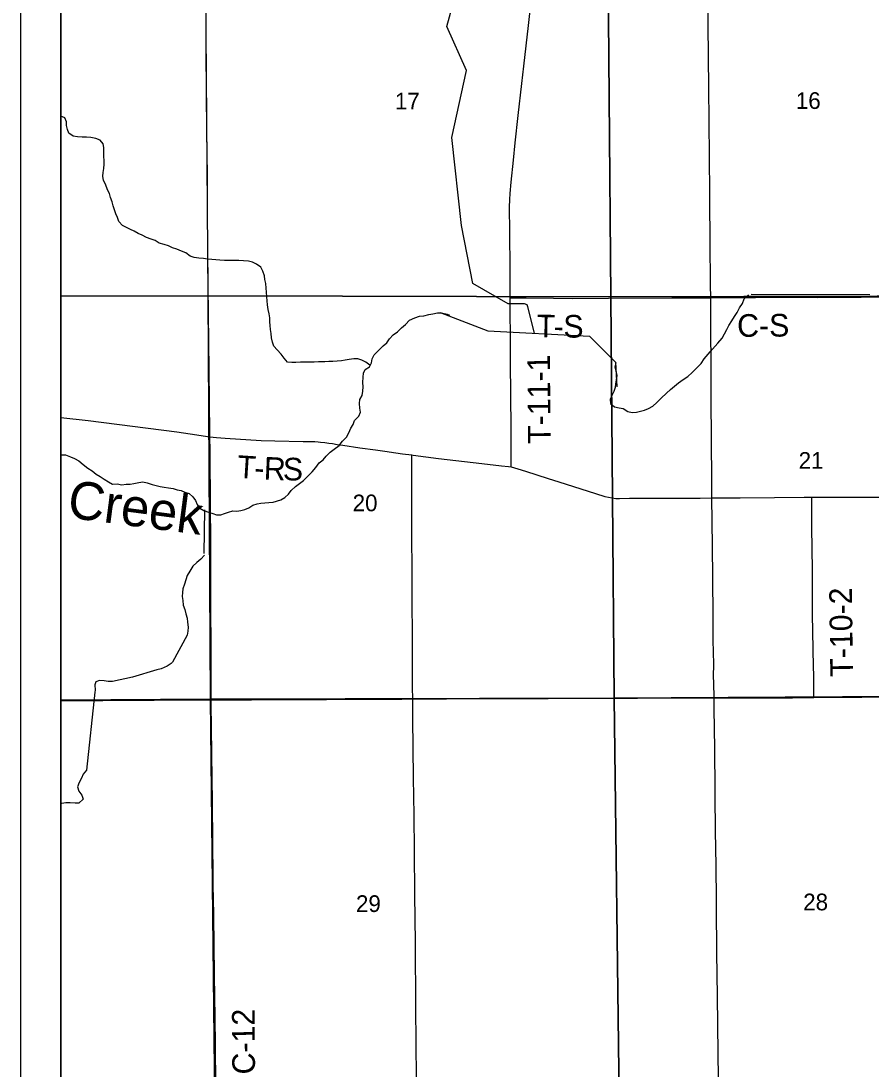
# Model space of a CAD drawing. Extents: x 0 to 34, y 0 to 22.
# Drawn here: x 23.417 to 25.546, y 16.699 to 19.326 of the extents above; entities that cross this region are included whole.
import ezdxf

# ---------------------------------------------------------------- set-up
doc = ezdxf.new("R2010")
doc.units = 0
for name, color, linetype in [('GM_X_County_Road', 7, 'Continuous'), ('GM_X_County_Road_Text', 7, 'Continuous'), ('GM_X_Minor_River', 7, 'Continuous'), ('GM_X_Minor_River_Text', 7, 'Continuous'), ('GM_X_Section', 7, 'Continuous'), ('GM_X_Section_Text', 7, 'Continuous'), ('GM_X_Township_Road', 7, 'Continuous'), ('GM_X_Township_Road_Text', 7, 'Continuous'), ('GM_X_US_Route', 7, 'Continuous'), ('SC_Scratch1', 7, 'Continuous'), ('SH_Data', 7, 'Continuous')]:
    doc.layers.add(name, color=color, linetype=linetype)

msp = doc.modelspace()

# ---------------------------------------------------------------- linework, layer by layer
at = {"layer": 'GM_X_County_Road'}
for points in [[(23.8901, 18.2832), (23.89, 18.2923), (23.8882, 18.4509), (23.886, 18.6623), (23.8844, 18.8488), (23.8839, 18.9265), (23.8836, 18.9483), (23.8833, 18.9825), (23.8824, 19.0602), (23.8818, 19.1348), (23.881, 19.2623), (23.8805, 19.3369), (23.8781, 19.5887), (23.8777, 19.6313)], [(25.1452, 18.632), (25.1445, 18.6646), (25.1437, 18.7733), (25.1433, 18.8012), (25.1429, 18.8477), (25.1424, 18.8944), (25.1408, 19.0747), (25.1401, 19.1582), (25.1393, 19.2357), (25.1387, 19.3165), (25.1382, 19.3693), (25.1379, 19.3812)], [(25.148, 18.1303), (25.1476, 18.1736), (25.1463, 18.3788), (25.1457, 18.4813), (25.1454, 18.5342), (25.1451, 18.6026), (25.1454, 18.6242), (25.1452, 18.632)], [(25.1452, 18.632), (25.2015, 18.6323), (25.2574, 18.6324), (25.304, 18.6331), (25.4128, 18.6328), (25.5216, 18.6336), (25.5869, 18.6341), (25.7485, 18.6348), (25.8945, 18.6357)], [(23.5167, 18.3321), (23.5849, 18.3241), (23.807, 18.2961), (23.8408, 18.2914), (23.8901, 18.2832)], [(23.8934, 17.6243), (23.8936, 17.6615), (23.8933, 17.6926), (23.8933, 17.7641), (23.8926, 17.8481), (23.8926, 17.8884), (23.8921, 17.9411), (23.892, 17.9845), (23.892, 18.0343), (23.8913, 18.0996), (23.8914, 18.1462), (23.8908, 18.2084), (23.8907, 18.2488), (23.8901, 18.2832)], [(25.1534, 17.6295), (25.1523, 17.6673), (25.1521, 17.6827), (25.1524, 17.7136), (25.1513, 17.7739), (25.1511, 17.8329), (25.15, 17.9311), (25.1494, 18.0088), (25.1486, 18.071), (25.148, 18.1303)], [(23.9049, 16.6197), (23.9048, 16.6263), (23.9045, 16.6667), (23.903, 16.8346), (23.9026, 16.875), (23.9006, 17.0056), (23.8996, 17.0864), (23.8985, 17.161), (23.8971, 17.2885), (23.897, 17.3071), (23.8967, 17.3289), (23.8966, 17.3475), (23.8962, 17.3693), (23.8954, 17.4253), (23.8947, 17.4905), (23.8933, 17.6149), (23.8934, 17.6243)], [(25.1644, 16.6302), (25.1644, 16.6391), (25.1641, 16.6764), (25.1634, 16.7386), (25.1617, 16.8816), (25.1603, 16.9903), (25.1593, 17.1051), (25.1592, 17.1327), (25.1575, 17.2632), (25.157, 17.2847), (25.1567, 17.3248), (25.1562, 17.3557), (25.1558, 17.3991), (25.1547, 17.5016), (25.1535, 17.6025), (25.1534, 17.6272), (25.1534, 17.6295)]]:
    msp.add_lwpolyline(points, dxfattribs=at)
at = {"layer": 'GM_X_Minor_River'}
for points in [[(24.7033, 18.543), (24.6869, 18.6095), (24.6851, 18.6141), (24.6779, 18.6168), (24.6673, 18.6169), (24.6369, 18.6164), (24.5484, 18.6678), (24.5208, 18.8134), (24.4962, 19.0334), (24.5329, 19.2019), (24.4836, 19.312), (24.5085, 19.404)], [(23.5477, 19.037), (23.5364, 19.0444), (23.5331, 19.0539), (23.5305, 19.0638), (23.531, 19.0733), (23.5266, 19.0828), (23.5168, 19.0871), (23.5167, 19.0871)], [(24.2907, 18.4635), (24.2809, 18.4704), (24.2711, 18.4758), (24.2606, 18.479), (24.2503, 18.4791), (24.2386, 18.4773), (24.2291, 18.4759), (24.2196, 18.4741), (24.2086, 18.473), (24.1983, 18.472), (24.1881, 18.4721), (24.1778, 18.4718), (24.1623, 18.4712), (24.1513, 18.4702), (24.1407, 18.4703), (24.1285, 18.4708), (24.1168, 18.4705), (24.1054, 18.4699), (24.0956, 18.47), (24.0842, 18.4708), (24.0763, 18.4804), (24.0685, 18.4907), (24.0584, 18.5011), (24.0505, 18.5106), (24.0468, 18.5205), (24.0443, 18.5316), (24.0433, 18.5426), (24.0422, 18.5525), (24.0408, 18.5623), (24.0402, 18.5718), (24.0399, 18.5813), (24.0381, 18.592), (24.0363, 18.603), (24.0345, 18.6144), (24.0335, 18.6247), (24.0329, 18.6341), (24.0319, 18.6463), (24.0312, 18.6562), (24.0298, 18.6676), (24.0276, 18.6778), (24.0266, 18.6873), (24.0229, 18.6988), (24.0174, 18.7091), (24.0068, 18.7164), (23.9966, 18.7214), (23.9864, 18.7238), (23.9739, 18.7247), (23.9626, 18.7252), (23.9508, 18.7257), (23.9375, 18.7258), (23.9265, 18.7251), (23.9148, 18.7264), (23.905, 18.7273), (23.8947, 18.7277), (23.8841, 18.7286), (23.8739, 18.7302), (23.8622, 18.7311), (23.8504, 18.7327), (23.8406, 18.7366), (23.8297, 18.7447), (23.8191, 18.749), (23.8074, 18.7536), (23.7965, 18.7575), (23.7867, 18.7618), (23.7753, 18.7653), (23.7632, 18.7689), (23.7527, 18.7758), (23.7425, 18.7786), (23.7312, 18.7832), (23.7202, 18.789), (23.7104, 18.7929), (23.7006, 18.7991), (23.6908, 18.8034), (23.6712, 18.8134), (23.6618, 18.823), (23.6585, 18.8329), (23.6541, 18.8424), (23.6508, 18.8527), (23.6478, 18.8626), (23.6453, 18.8725), (23.6409, 18.8836), (23.6387, 18.8931), (23.6335, 18.9026), (23.6283, 18.9163), (23.6235, 18.9259), (23.6217, 18.9365), (23.6222, 18.946), (23.6242, 18.9562), (23.6251, 18.9665), (23.6248, 18.9763), (23.6245, 18.9858), (23.6242, 18.9972), (23.624, 19.0082), (23.6226, 19.0177), (23.6147, 19.0273), (23.6045, 19.0308), (23.592, 19.034), (23.5807, 19.0348), (23.57, 19.0345), (23.5579, 19.0354), (23.5477, 19.037)], [(24.9068, 18.4688), (24.9048, 18.4586), (24.9073, 18.4479), (24.9095, 18.4373), (24.9082, 18.4267), (24.9062, 18.4164), (24.9054, 18.407), (24.9018, 18.3971), (24.8968, 18.3869), (24.8929, 18.3767), (24.8936, 18.3668), (24.9041, 18.3588), (24.9151, 18.3564), (24.9256, 18.3544), (24.9373, 18.3471), (24.9479, 18.3443), (24.9585, 18.3453), (24.9688, 18.3479), (24.9787, 18.3504), (24.9893, 18.3549), (25, 18.3605), (25.0096, 18.3695), (25.0203, 18.3808), (25.0337, 18.3932), (25.0444, 18.4018), (25.0544, 18.4108), (25.0639, 18.4187), (25.0758, 18.4269), (25.0876, 18.4348), (25.098, 18.4449), (25.1083, 18.4551), (25.1206, 18.4671), (25.1287, 18.4788), (25.1383, 18.4904), (25.149, 18.5028), (25.1628, 18.5183), (25.1732, 18.5311), (25.179, 18.5416), (25.1852, 18.5522), (25.1902, 18.5624), (25.1979, 18.5745), (25.2045, 18.5854), (25.2114, 18.5952), (25.2172, 18.6065), (25.2246, 18.6179), (25.2285, 18.6292), (25.2384, 18.6382), (25.2407, 18.6386)], [(25.2464, 18.6408), (25.5436, 18.6398)], [(24.3012, 18.4888), (24.3238, 18.5114), (24.3334, 18.5188), (24.3396, 18.5287), (24.3495, 18.5388), (24.3602, 18.5467), (24.3698, 18.5564), (24.3801, 18.5654), (24.3905, 18.5756), (24.4031, 18.5819), (24.4152, 18.586), (24.4262, 18.587), (24.4384, 18.5899), (24.4487, 18.5921), (24.46, 18.5939), (24.4707, 18.5945), (24.4843, 18.591), (24.4907, 18.5883)], [(24.4669, 18.5953), (24.5866, 18.549), (24.8415, 18.5359), (24.906, 18.4703), (24.9092, 18.4084)], [(24.2385, 18.2936), (24.2431, 18.3049), (24.2493, 18.3147), (24.2521, 18.3246), (24.2632, 18.3355), (24.2671, 18.3457), (24.2657, 18.3556), (24.265, 18.367), (24.2655, 18.3772), (24.2713, 18.3874), (24.2733, 18.398), (24.2738, 18.4086), (24.2736, 18.42), (24.2737, 18.4333), (24.2746, 18.4428), (24.2792, 18.4526), (24.2899, 18.4589), (24.2953, 18.4691), (24.2966, 18.479), (24.3012, 18.4888)], [(23.5167, 18.2386), (23.518, 18.2385), (23.5279, 18.238), (23.5411, 18.2333), (23.5509, 18.229), (23.5618, 18.2232), (23.5727, 18.214), (23.584, 18.2052), (23.5949, 18.1982), (23.6051, 18.1902), (23.6152, 18.1844), (23.6254, 18.1771), (23.6363, 18.1705), (23.6461, 18.1647), (23.6575, 18.1654), (23.6692, 18.1634), (23.6802, 18.1651), (23.6901, 18.165), (23.6996, 18.1665), (23.7121, 18.169), (23.7216, 18.1704), (23.7326, 18.168), (23.7454, 18.1641), (23.7553, 18.1614), (23.7658, 18.159), (23.7757, 18.1577), (23.7859, 18.1557), (23.798, 18.1541), (23.8078, 18.1506), (23.8177, 18.1486), (23.8275, 18.1447), (23.8377, 18.1412), (23.8474, 18.1331), (23.8538, 18.1236), (23.8578, 18.1141), (23.8649, 18.1045), (23.8751, 18.0991), (23.8864, 18.0948), (23.897, 18.0917), (23.9068, 18.0881), (23.9175, 18.088), (23.927, 18.091), (23.9369, 18.0943), (23.9471, 18.0984), (23.9577, 18.0971), (23.9676, 18.0985), (23.9779, 18.1015), (23.9874, 18.1059), (23.9977, 18.1119), (24.0084, 18.1156), (24.0178, 18.117), (24.0273, 18.1177), (24.0376, 18.1191), (24.0486, 18.1201), (24.0676, 18.126), (24.0775, 18.1316), (24.0871, 18.1395), (24.094, 18.1493), (24.1044, 18.1594), (24.1147, 18.1669), (24.1246, 18.1744), (24.1353, 18.1846), (24.1464, 18.1958), (24.1557, 18.2067), (24.1641, 18.2184), (24.1737, 18.2255), (24.1817, 18.2353), (24.1913, 18.2451), (24.2016, 18.2526), (24.2135, 18.2616), (24.2223, 18.2729), (24.2323, 18.283), (24.2385, 18.2936)], [(23.8766, 18.1002), (23.8751, 17.9913)], [(23.8762, 17.9867), (23.8677, 17.977), (23.857, 17.9683), (23.8471, 17.9597), (23.8401, 17.9472), (23.8332, 17.9359), (23.83, 17.925), (23.8261, 17.9144), (23.8218, 17.9026), (23.8213, 17.8932), (23.8205, 17.8833), (23.8226, 17.8734), (23.8233, 17.862), (23.8269, 17.8506), (23.8298, 17.8396), (23.8328, 17.8289), (23.8342, 17.819), (23.8352, 17.8069), (23.8347, 17.7966), (23.8327, 17.7868)], [(23.8327, 17.7868), (23.7963, 17.7188), (23.7932, 17.7151), (23.7829, 17.7084), (23.7681, 17.7024), (23.757, 17.6995), (23.6958, 17.6815), (23.6464, 17.6702)], [(23.6464, 17.6702), (23.635, 17.6703), (23.6252, 17.6723), (23.6138, 17.6728), (23.6039, 17.6691), (23.6016, 17.6616), (23.6022, 17.6487), (23.6016, 17.6433)], [(23.6016, 17.6433), (23.5806, 17.4485)], [(23.5806, 17.4485), (23.5722, 17.438), (23.5683, 17.4278), (23.5621, 17.4168), (23.5586, 17.4062), (23.5619, 17.3959), (23.5689, 17.3852), (23.5726, 17.3757), (23.5619, 17.3656), (23.5524, 17.3653), (23.5403, 17.3662), (23.5293, 17.3659), (23.519, 17.3649), (23.5167, 17.3643)]]:
    msp.add_lwpolyline(points, dxfattribs=at)
at = {"layer": 'GM_X_Section'}
for points in [[(23.5167, 19.6297), (23.5167, 18.6363), (23.8857, 18.6369), (23.8779, 19.6309)], [(23.8779, 19.6309), (24.8865, 19.6346), (24.8949, 18.6346), (23.8857, 18.6369)], [(24.8865, 19.6346), (25.8865, 19.646), (25.8948, 18.6366), (24.8949, 18.6346)], [(23.5167, 18.6363), (23.5167, 17.6239), (23.8913, 17.6257), (23.8857, 18.6369)], [(23.8857, 18.6369), (24.8949, 18.6346), (24.9025, 17.6286), (23.8913, 17.6257)], [(24.8949, 18.6346), (25.8948, 18.6366), (25.9035, 17.634), (24.9025, 17.6286)], [(23.5167, 17.6239), (23.5167, 16.6195), (23.9023, 16.6215), (23.8913, 17.6257)], [(23.8913, 17.6257), (24.9025, 17.6286), (24.9155, 16.6278), (23.9023, 16.6215)], [(24.9025, 17.6286), (25.9035, 17.634), (25.9123, 16.6303), (24.9155, 16.6278)]]:
    msp.add_lwpolyline(points, close=True, dxfattribs=at)
at = {"layer": 'GM_X_Township_Road'}
msp.add_line((24.6426, 18.59), (24.6424, 18.632), dxfattribs=at)
for points in [[(24.6424, 18.632), (24.6421, 18.7037), (24.6418, 18.797), (24.641, 18.8593), (24.6413, 18.878), (24.6421, 18.8935), (24.6447, 18.9214), (24.6506, 18.9771), (24.6548, 19.0205), (24.6623, 19.0885), (24.6717, 19.1689), (24.6768, 19.2121), (24.6886, 19.3141), (24.6961, 19.3822)], [(24.6424, 18.632), (24.6826, 18.6321), (24.7511, 18.6306), (24.7979, 18.6305), (24.8883, 18.6313), (25.0472, 18.632), (25.1314, 18.6319), (25.1452, 18.632)], [(24.645, 18.2079), (24.645, 18.237), (24.6446, 18.3055), (24.6433, 18.4704), (24.6428, 18.5419), (24.6426, 18.59)], [(23.8901, 18.2832), (23.9065, 18.2816), (23.9283, 18.2801), (24.0183, 18.2747), (24.0525, 18.2734), (24.124, 18.2722), (24.1426, 18.2719), (24.1532, 18.2717), (24.1616, 18.2711), (24.1672, 18.2705), (24.1776, 18.2695), (24.1876, 18.2679), (24.1972, 18.2665), (24.2091, 18.2644), (24.2228, 18.2627), (24.2659, 18.2563), (24.3053, 18.2508), (24.3283, 18.2474), (24.3558, 18.2434), (24.3729, 18.241), (24.3956, 18.238)], [(24.3956, 18.238), (24.3989, 18.2377), (24.463, 18.2292), (24.5495, 18.2192), (24.5711, 18.2164), (24.6205, 18.2105), (24.6381, 18.2088), (24.645, 18.2079)], [(24.3986, 17.6265), (24.398, 17.6556), (24.3978, 17.6867), (24.3978, 17.7333), (24.3976, 17.7737), (24.3967, 17.8826), (24.3964, 17.9573), (24.3963, 18.0259), (24.396, 18.1282), (24.3958, 18.2048), (24.3956, 18.238)], [(24.645, 18.2079), (24.6529, 18.2058), (24.6613, 18.2034), (24.6809, 18.1971), (24.7372, 18.1791), (24.7639, 18.171), (24.8558, 18.1417), (24.8796, 18.1343), (24.8886, 18.132), (24.8979, 18.1303), (24.9072, 18.1293), (24.9166, 18.129), (24.9415, 18.1294), (24.9788, 18.1298), (25.1187, 18.13), (25.148, 18.1303)], [(25.148, 18.1303), (25.184, 18.1306), (25.2182, 18.1307), (25.3046, 18.1316), (25.3789, 18.1319), (25.3982, 18.1319)], [(25.4028, 17.6302), (25.4031, 17.6366), (25.4032, 17.6397), (25.4035, 17.6521), (25.4028, 17.6801), (25.4016, 17.7454), (25.4008, 17.8013), (25.4, 17.8324), (25.4001, 17.8759), (25.3994, 17.9505), (25.3985, 18.0561), (25.398, 18.1152), (25.3982, 18.1319)], [(25.3982, 18.1319), (25.5718, 18.1326), (25.6847, 18.1327), (25.7391, 18.1333), (25.8007, 18.1333), (25.8669, 18.1342), (25.8986, 18.1345)], [(24.4081, 16.6235), (24.4075, 16.676), (24.4062, 16.8533), (24.4048, 17.015), (24.4037, 17.1363), (24.4026, 17.2452), (24.4015, 17.3353), (24.4012, 17.3819), (24.4003, 17.4286), (24.3988, 17.5779), (24.3987, 17.6214), (24.3986, 17.6265)]]:
    msp.add_lwpolyline(points, dxfattribs=at)
at = {"layer": 'GM_X_US_Route'}
msp.add_lwpolyline([(23.5167, 17.622), (23.6217, 17.6225), (23.8796, 17.6243), (23.8934, 17.6243), (23.9946, 17.6248), (24.3706, 17.6264), (24.3986, 17.6265), (24.4825, 17.6269), (24.6503, 17.6276), (24.7, 17.6275), (24.7373, 17.6279), (24.8088, 17.6283), (24.9052, 17.6285), (24.9611, 17.6289), (25.0947, 17.6292), (25.1534, 17.6295), (25.1631, 17.6296), (25.2097, 17.6296), (25.3496, 17.6297), (25.4028, 17.6302), (25.5236, 17.6313), (25.8033, 17.6338)], dxfattribs=at)
at = {"layer": 'SC_Scratch1'}
msp.add_lwpolyline([(23.5167, 20.6789), (23.5167, 15.3175), (30.3167, 15.3175), (30.3167, 20.8109), (30.0181, 20.8047), (28.8862, 20.7941), (27.8891, 20.7835), (26.8843, 20.7634), (25.88, 20.7414), (25.1253, 20.7174), (23.8668, 20.6853)], close=True, dxfattribs=at)
at = {"layer": 'SH_Data'}
for points in [[(23.4167, 21), (30.4167, 21), (30.4167, 14), (23.4167, 14)], [(23.5167, 20.9), (30.3167, 20.9), (30.3167, 15.3175), (23.5167, 15.3175)]]:
    msp.add_lwpolyline(points, close=True, dxfattribs=at)

# ---------------------------------------------------------------- texts
at = {"layer": 'GM_X_County_Road_Text'}
for s, rotation, p in [('C-S', 0.4302, (25.2111, 18.5339)), ('C-12', 90.3442, (24.0031, 16.6857))]:
    msp.add_text(s, height=0.05682, rotation=rotation, dxfattribs=at).set_placement(p)
at = {"layer": 'GM_X_Minor_River_Text'}
msp.add_text('Creek', height=0.09476, rotation=352.5393, dxfattribs=at).set_placement((23.5304, 18.0817))
at = {"layer": 'GM_X_Section_Text'}
for s, p in [('17', (24.3535, 19.104)), ('16', (25.3581, 19.1052)), ('21', (25.3652, 18.2034)), ('20', (24.2477, 18.0969)), ('29', (24.256, 17.0927)), ('28', (25.3765, 17.0969))]:
    msp.add_text(s, height=0.04186, rotation=0, dxfattribs=at).set_placement(p)
at = {"layer": 'GM_X_Township_Road_Text'}
for s, height, rotation, p in [('T', 0.0568, 358.9242, (24.7083, 18.5331)), ('S', 0.0568, 0.3199, (24.7757, 18.5319)), ('-', 0.0568, 359.1009, (24.751, 18.5323)), ('T-11-1', 0.05682, 90.4943, (24.7438, 18.2661)), ('T', 0.0568, 356.2903, (23.9571, 18.1808)), ('R', 0.0568, 357.6189, (24.0242, 18.1766)), ('S', 0.0568, 359.0175, (24.0724, 18.1746)), ('-', 0.0568, 356.635, (23.9999, 18.178)), ('T-10-2', 0.05682, 90.7388, (25.5013, 17.6825))]:
    msp.add_text(s, height=height, rotation=rotation, dxfattribs=at).set_placement(p)

doc.saveas('drawing.dxf')
